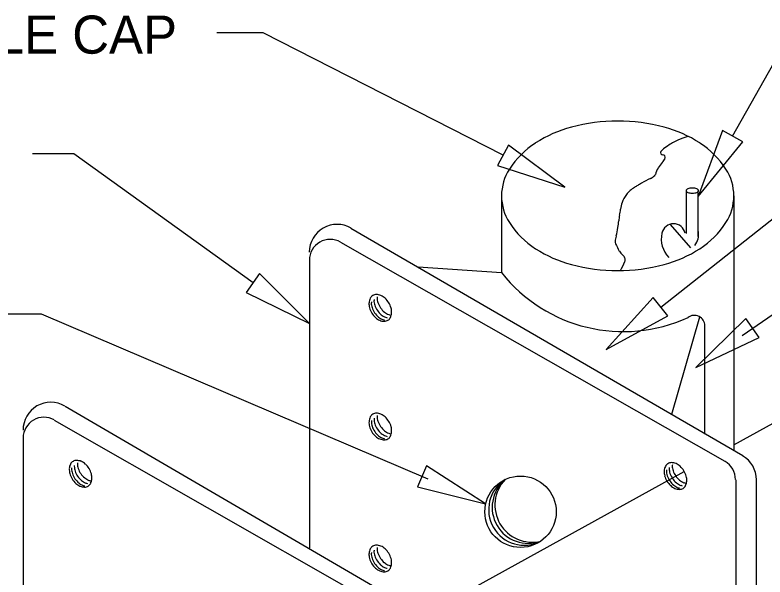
# Model space of a CAD drawing. Extents: x -1551.93 to -1544.71, y 2060.77 to 2070.61.
# Drawn here: x -1549.207 to -1548.026, y 2069.721 to 2070.606 of the extents above; entities that cross this region are included whole.
import ezdxf

# ---------------------------------------------------------------- set-up
doc = ezdxf.new("R2010")
doc.units = 0
for name, color, linetype in [('DETL-DIMS', 7, 'Continuous'), ('DETL-LINE', 7, 'Continuous'), ('DETL-NOTE', 7, 'Continuous')]:
    doc.layers.add(name, color=color, linetype=linetype)

msp = doc.modelspace()

# ---------------------------------------------------------------- linework, layer by layer
at = {"layer": 'DETL-DIMS'}
for p, q in [((-1548.0776, 2070.415), (-1547.9806, 2070.587)), ((-1548.8166, 2070.578), (-1548.8896, 2070.578)), ((-1548.4386, 2070.385), (-1548.8166, 2070.578)), ((-1548.1906, 2070.146), (-1547.8386, 2070.424)), ((-1549.1146, 2070.387), (-1549.1796, 2070.387)), ((-1548.8326, 2070.184), (-1549.1146, 2070.387)), ((-1548.0626, 2070.101), (-1547.8356, 2070.259)), ((-1549.1656, 2070.135), (-1549.4676, 2070.135)), ((-1548.5566, 2069.875), (-1549.1656, 2070.135)), ((-1548.0756, 2069.929), (-1547.9386, 2070.005)), ((-1548.5636, 2069.661), (-1548.1536, 2069.887))]:
    msp.add_line(p, q, dxfattribs=at)
for points in [[(-1548.0616, 2070.406), (-1548.0936, 2070.424), (-1548.1316, 2070.32)], [(-1548.4306, 2070.401), (-1548.4476, 2070.369), (-1548.3416, 2070.335)], [(-1548.8226, 2070.199), (-1548.8436, 2070.169), (-1548.7436, 2070.12)], [(-1548.1796, 2070.132), (-1548.2026, 2070.161), (-1548.2766, 2070.079)], [(-1548.0356, 2070.098), (-1548.0566, 2070.128), (-1548.1356, 2070.051)], [(-1548.5596, 2069.896), (-1548.5736, 2069.863), (-1548.4666, 2069.836)]]:
    msp.add_lwpolyline(points, close=True, dxfattribs=at)
at = {"layer": 'DETL-LINE'}
for p, q in [((-1548.1506, 2070.329), (-1548.1506, 2070.262)), ((-1548.1316, 2070.257), (-1548.1316, 2070.329)), ((-1548.4416, 2070.321), (-1548.4416, 2070.2)), ((-1548.0756, 2070.321), (-1548.0756, 2069.92)), ((-1548.6786, 2070.27), (-1548.0616, 2069.912)), ((-1548.1756, 2070.276), (-1548.1436, 2070.239)), ((-1548.6946, 2070.248), (-1548.0896, 2069.903)), ((-1548.7436, 2070.22), (-1548.7436, 2069.766)), ((-1548.4416, 2070.2), (-1548.5726, 2070.209)), ((-1548.1296, 2070.13), (-1548.1736, 2069.977)), ((-1548.1216, 2070.116), (-1548.1216, 2069.946)), ((-1549.1286, 2069.99), (-1548.5456, 2069.65)), ((-1549.1456, 2069.968), (-1548.5726, 2069.641)), ((-1549.1946, 2069.94), (-1549.1946, 2069.507)), ((-1548.0726, 2069.874), (-1548.0726, 2069.414)), ((-1548.0406, 2069.874), (-1548.0406, 2069.413))]:
    msp.add_line(p, q, dxfattribs=at)
msp.add_circle((-1548.4114, 2069.8236), 0.0562, dxfattribs=at)
for centre, radius, start, end in [((-1548.2584, 2070.1559), 0.283, 90, 104.9368), ((-1548.2584, 2070.1559), 0.283, 75.0632, 90), ((-1548.2801, 2070.2373), 0.1987, 104.9368, 122.7829), ((-1548.2367, 2070.2373), 0.1987, 57.2171, 75.0632), ((-1548.1225, 2070.3176), 0.1001, 114.4559, 124.7154), ((-1548.1223, 2070.3171), 0.1006, 104.2226, 114.4559), ((-1548.3133, 2070.2887), 0.1375, 122.7829, 147.2527), ((-1548.0875, 2070.267), 0.1616, 124.7154, 128.6761), ((-1548.2036, 2070.2887), 0.1375, 32.7473, 57.2171), ((-1548.1876, 2070.3891), 0.00345, 144.3395, 271.8271), ((-1548.1819, 2070.385), 0.0104, 128.6761, 144.3395), ((-1548.1873, 2070.3818), 0.00385, 335.5, 91.8271), ((-1548.1569, 2070.3436), 0.0434, 136.3012, 150.5406), ((-1548.2057, 2070.3901), 0.024, 316.3012, 335.5), ((-1548.3636, 2070.3211), 0.0777, 147.2527, 180), ((-1548.1478, 2070.3384), 0.0539, 150.5406, 162.2182), ((-1548.1533, 2070.3211), 0.0777, 0, 32.7473), ((-1548.1261, 2070.1799), 0.1869, 115.6278, 120.4952), ((-1548.2209, 2070.3775), 0.0323, 295.6278, 307.36), ((-1548.2051, 2070.3568), 0.00622, 307.36, 342.2182), ((-1547.9262, 2069.8365), 0.5842, 120.9785, 121.5501), ((-1547.8064, 2069.637), 0.8169, 120.4952, 120.9785), ((-1548.2053, 2070.2911), 0.0508, 121.5501, 140.727), ((-1548.149, 2070.3293), 0.00185, 134.8586, 180), ((-1548.149, 2070.3293), 0.00185, 180, 225.1414), ((-1548.1452, 2070.3255), 0.0072, 112.4002, 134.8586), ((-1548.1452, 2070.3331), 0.0072, 225.1414, 247.5998), ((-1548.1427, 2070.3194), 0.0139, 99.6886, 112.4002), ((-1548.1427, 2070.3393), 0.0139, 247.5998, 260.3114), ((-1548.141, 2070.3096), 0.0238, 90, 99.6886), ((-1548.141, 2070.3491), 0.0238, 260.3114, 270), ((-1548.141, 2070.3096), 0.0238, 80.3114, 90), ((-1548.141, 2070.3491), 0.0238, 270, 279.6886), ((-1548.1393, 2070.3194), 0.0139, 67.5998, 80.3114), ((-1548.1393, 2070.3393), 0.0139, 279.6886, 292.4002), ((-1548.1368, 2070.3255), 0.0072, 45.1414, 67.5998), ((-1548.1368, 2070.3331), 0.0072, 292.4002, 314.8586), ((-1548.133, 2070.3293), 0.00185, 0, 45.1414), ((-1548.133, 2070.3293), 0.00185, 314.8586, 0), ((-1548.3636, 2070.3211), 0.0777, 180, 212.7473), ((-1548.2153, 2070.2993), 0.0378, 140.727, 162.9839), ((-1548.1533, 2070.3211), 0.0777, 327.2527, 0), ((-1548.1539, 2070.2776), 0.1028, 167.4783, 172.6817), ((-1548.1197, 2070.2701), 0.1378, 162.9839, 167.4783), ((-1547.9716, 2070.2542), 0.2865, 172.6817, 174.5027), ((-1548.3133, 2070.3534), 0.1375, 212.7473, 237.2171), ((-1548.6472, 2070.3192), 0.3922, 352.9461, 354.5027), ((-1548.1705, 2070.2583), 0.0188, 12.4028, 167.5972), ((-1548.2036, 2070.3534), 0.1375, 302.7829, 327.2527), ((-1548.7002, 2070.2324), 0.0438, 59.8138, 180), ((-1548.329, 2070.2799), 0.0715, 342.0846, 352.9461), ((-1548.1613, 2070.261), 0.0304, 323.4347, 7.5849), ((-1548.7111, 2070.2198), 0.0328, 60.2969, 180), ((-1548.2327, 2070.2487), 0.0297, 162.0846, 178.9743), ((-1548.1478, 2070.2533), 0.042, 167.5972, 224.2626), ((-1548.2537, 2070.2491), 0.0087, 178.9743, 203.1865), ((-1548.159, 2070.2897), 0.1117, 203.1865, 209.8962), ((-1548.2801, 2070.4049), 0.1987, 237.2171, 255.0632), ((-1548.2365, 2070.2451), 0.0222, 209.8962, 231.1328), ((-1548.2367, 2070.4049), 0.1987, 284.9368, 302.7829), ((-1548.3679, 2070.2678), 0.1308, 330.4837, 337.392), ((-1548.2574, 2070.2191), 0.0111, 20.8484, 51.1328), ((-1548.2541, 2070.2204), 0.00755, 337.392, 20.8484), ((-1548.2584, 2070.4863), 0.283, 255.0632, 270), ((-1548.2584, 2070.4863), 0.283, 270, 284.9368), ((-1548.2495, 2070.3518), 0.2445, 218.3349, 294.647), ((-1548.6325, 2070.1517), 0.0175, 152.7723, 177.2015), ((-1548.6384, 2070.1548), 0.0109, 121.5859, 152.7723), ((-1548.6384, 2070.1548), 0.0109, 90.3995, 121.5859), ((-1548.6384, 2070.1481), 0.0175, 65.9703, 90.3995), ((-1548.6196, 2070.1607), 0.0175, 175.5761, 179.972), ((-1548.613, 2070.1607), 0.0242, 179.972, 198.5308), ((-1548.6411, 2070.142), 0.0242, 47.4114, 65.9703), ((-1548.6472, 2070.1354), 0.0332, 31.5859, 47.4114), ((-1548.6259, 2070.1514), 0.0242, 177.2015, 195.7604), ((-1548.6288, 2070.1527), 0.0175, 175.5761, 179.972), ((-1548.6222, 2070.1527), 0.0242, 179.972, 198.5308), ((-1548.6246, 2070.1564), 0.0175, 175.5761, 179.972), ((-1548.618, 2070.1564), 0.0242, 179.972, 198.5308), ((-1548.6094, 2070.1593), 0.0332, 198.5308, 214.3563), ((-1548.6045, 2070.1635), 0.0332, 198.5308, 214.3563), ((-1548.6472, 2070.1354), 0.0332, 15.7604, 31.5859), ((-1548.6172, 2070.1538), 0.0332, 195.7604, 211.5859), ((-1548.6172, 2070.1538), 0.0332, 211.5859, 227.4114), ((-1548.6137, 2070.1556), 0.0332, 198.5308, 214.3563), ((-1548.6137, 2070.1556), 0.0332, 214.3563, 230.1818), ((-1548.6094, 2070.1593), 0.0332, 214.3563, 230.1818), ((-1548.6045, 2070.1635), 0.0332, 214.3563, 230.1818), ((-1548.6102, 2070.1566), 0.0242, 230.1818, 248.7407), ((-1548.6319, 2070.1375), 0.0175, 332.7723, 357.2015), ((-1548.6385, 2070.1378), 0.0242, 357.2015, 15.7604), ((-1548.6233, 2070.1472), 0.0242, 227.4114, 245.9703), ((-1548.6194, 2070.1487), 0.0242, 230.1818, 248.7407), ((-1548.626, 2070.1411), 0.0175, 245.9703, 270.3995), ((-1548.6152, 2070.1524), 0.0242, 230.1818, 248.7407), ((-1548.6218, 2070.1425), 0.0175, 248.7407, 257.6351), ((-1548.6259, 2070.1345), 0.0109, 270.3995, 301.5859), ((-1548.6176, 2070.1462), 0.0175, 248.7407, 257.6351), ((-1548.6259, 2070.1345), 0.0109, 301.5859, 332.7723), ((-1548.6126, 2070.1504), 0.0175, 248.7407, 257.6351), ((-1548.1376, 2070.1165), 0.0164, 0, 127.5357), ((-1549.1509, 2069.9522), 0.0438, 59.8138, 180), ((-1549.1618, 2069.9396), 0.0328, 60.2969, 180), ((-1548.6324, 2069.9648), 0.0175, 152.7723, 177.2015), ((-1548.6384, 2069.9679), 0.0109, 121.5859, 152.7723), ((-1548.6384, 2069.9679), 0.0109, 90.3995, 121.5859), ((-1548.6245, 2069.9696), 0.0175, 175.5761, 179.972), ((-1548.6179, 2069.9696), 0.0242, 179.972, 198.5308), ((-1548.6383, 2069.9612), 0.0175, 65.9703, 90.3995), ((-1548.6196, 2069.9738), 0.0175, 175.5761, 179.972), ((-1548.613, 2069.9738), 0.0242, 179.972, 198.5308), ((-1548.641, 2069.9551), 0.0242, 47.4114, 65.9703), ((-1548.6471, 2069.9485), 0.0332, 31.5859, 47.4114), ((-1548.6258, 2069.9645), 0.0242, 177.2015, 195.7604), ((-1548.6172, 2069.9669), 0.0332, 195.7604, 211.5859), ((-1548.6288, 2069.9659), 0.0175, 175.5761, 179.972), ((-1548.6221, 2069.9658), 0.0242, 179.972, 198.5308), ((-1548.6136, 2069.9687), 0.0332, 198.5308, 214.3563), ((-1548.6094, 2069.9724), 0.0332, 198.5308, 214.3563), ((-1548.6044, 2069.9767), 0.0332, 198.5308, 214.3563), ((-1548.6044, 2069.9767), 0.0332, 214.3563, 230.1818), ((-1548.6471, 2069.9485), 0.0332, 15.7604, 31.5859), ((-1548.6385, 2069.951), 0.0242, 357.2015, 15.7604), ((-1548.6172, 2069.9669), 0.0332, 211.5859, 227.4114), ((-1548.6136, 2069.9687), 0.0332, 214.3563, 230.1818), ((-1548.6094, 2069.9724), 0.0332, 214.3563, 230.1818), ((-1548.6151, 2069.9655), 0.0242, 230.1818, 248.7407), ((-1548.6102, 2069.9698), 0.0242, 230.1818, 248.7407), ((-1548.6126, 2069.9636), 0.0175, 248.7407, 257.6351), ((-1548.6318, 2069.9506), 0.0175, 332.7723, 357.2015), ((-1548.6232, 2069.9603), 0.0242, 227.4114, 245.9703), ((-1548.6194, 2069.9618), 0.0242, 230.1818, 248.7407), ((-1548.6259, 2069.9543), 0.0175, 245.9703, 270.3995), ((-1548.6218, 2069.9556), 0.0175, 248.7407, 257.6351), ((-1548.6259, 2069.9476), 0.0109, 270.3995, 301.5859), ((-1548.6175, 2069.9593), 0.0175, 248.7407, 257.6351), ((-1548.6259, 2069.9476), 0.0109, 301.5859, 332.7723), ((-1548.0838, 2069.8738), 0.0438, 0, 59.8138), ((-1549.1044, 2069.8906), 0.0175, 152.7723, 177.2015), ((-1549.1103, 2069.8936), 0.0109, 121.5859, 152.7723), ((-1549.1103, 2069.8936), 0.0109, 90.3995, 121.5859), ((-1549.1103, 2069.8869), 0.0175, 65.9703, 90.3995), ((-1549.0915, 2069.8995), 0.0175, 175.5761, 179.972), ((-1549.0849, 2069.8995), 0.0242, 179.972, 198.5308), ((-1549.113, 2069.8809), 0.0242, 47.4114, 65.9703), ((-1549.119, 2069.8743), 0.0332, 31.5859, 47.4114), ((-1548.1737, 2069.89), 0.0109, 121.5859, 152.7723), ((-1548.1737, 2069.89), 0.0109, 90.3995, 121.5859), ((-1548.1736, 2069.8834), 0.0175, 65.9703, 90.3995), ((-1548.1763, 2069.8773), 0.0242, 47.4114, 65.9703), ((-1548.1057, 2069.8744), 0.0328, 0, 60.2969), ((-1549.0977, 2069.8902), 0.0242, 177.2015, 195.7604), ((-1549.1007, 2069.8916), 0.0175, 175.5761, 179.972), ((-1549.0941, 2069.8916), 0.0242, 179.972, 198.5308), ((-1549.0965, 2069.8953), 0.0175, 175.5761, 179.972), ((-1549.0898, 2069.8953), 0.0242, 179.972, 198.5308), ((-1549.0813, 2069.8982), 0.0332, 198.5308, 214.3563), ((-1549.0764, 2069.9024), 0.0332, 198.5308, 214.3563), ((-1549.119, 2069.8743), 0.0332, 15.7604, 31.5859), ((-1548.1678, 2069.887), 0.0175, 152.7723, 177.2015), ((-1548.1611, 2069.8867), 0.0242, 177.2015, 195.7604), ((-1548.1641, 2069.888), 0.0175, 175.5761, 179.972), ((-1548.1575, 2069.888), 0.0242, 179.972, 198.5308), ((-1548.1599, 2069.8917), 0.0175, 175.5761, 179.972), ((-1548.1532, 2069.8917), 0.0242, 179.972, 198.5308), ((-1548.1549, 2069.896), 0.0175, 175.5761, 179.972), ((-1548.1483, 2069.896), 0.0242, 179.972, 198.5308), ((-1548.1397, 2069.8988), 0.0332, 198.5308, 214.3563), ((-1548.1824, 2069.8707), 0.0332, 31.5859, 47.4114), ((-1548.1824, 2069.8707), 0.0332, 15.7604, 31.5859), ((-1549.0891, 2069.8927), 0.0332, 195.7604, 211.5859), ((-1549.0891, 2069.8927), 0.0332, 211.5859, 227.4114), ((-1549.0855, 2069.8944), 0.0332, 198.5308, 214.3563), ((-1549.0855, 2069.8944), 0.0332, 214.3563, 230.1818), ((-1549.0813, 2069.8982), 0.0332, 214.3563, 230.1818), ((-1549.0764, 2069.9024), 0.0332, 214.3563, 230.1818), ((-1549.0821, 2069.8955), 0.0242, 230.1818, 248.7407), ((-1549.1038, 2069.8764), 0.0175, 332.7723, 357.2015), ((-1549.1104, 2069.8767), 0.0242, 357.2015, 15.7604), ((-1548.1525, 2069.8891), 0.0332, 195.7604, 211.5859), ((-1548.1489, 2069.8909), 0.0332, 198.5308, 214.3563), ((-1548.1447, 2069.8946), 0.0332, 198.5308, 214.3563), ((-1548.1447, 2069.8946), 0.0332, 214.3563, 230.1818), ((-1548.1397, 2069.8988), 0.0332, 214.3563, 230.1818), ((-1548.1738, 2069.8731), 0.0242, 357.2015, 15.7604), ((-1549.0952, 2069.8861), 0.0242, 227.4114, 245.9703), ((-1549.0913, 2069.8875), 0.0242, 230.1818, 248.7407), ((-1549.0979, 2069.88), 0.0175, 245.9703, 270.3995), ((-1549.0871, 2069.8913), 0.0242, 230.1818, 248.7407), ((-1549.0937, 2069.8814), 0.0175, 248.7407, 257.6351), ((-1549.0978, 2069.8733), 0.0109, 270.3995, 301.5859), ((-1549.0895, 2069.8851), 0.0175, 248.7407, 257.6351), ((-1549.0978, 2069.8733), 0.0109, 301.5859, 332.7723), ((-1549.0845, 2069.8893), 0.0175, 248.7407, 257.6351), ((-1548.4055, 2069.827), 0.0561, 122.664, 297.7204), ((-1548.3993, 2069.8306), 0.0568, 129.8655, 290.5188), ((-1548.3933, 2069.8341), 0.0584, 136.5705, 283.8138), ((-1548.1525, 2069.8891), 0.0332, 211.5859, 227.4114), ((-1548.1489, 2069.8909), 0.0332, 214.3563, 230.1818), ((-1548.1586, 2069.8825), 0.0242, 227.4114, 245.9703), ((-1548.1547, 2069.884), 0.0242, 230.1818, 248.7407), ((-1548.1505, 2069.8877), 0.0242, 230.1818, 248.7407), ((-1548.1455, 2069.8919), 0.0242, 230.1818, 248.7407), ((-1548.1529, 2069.8815), 0.0175, 248.7407, 257.6351), ((-1548.1612, 2069.8697), 0.0109, 301.5859, 332.7723), ((-1548.1479, 2069.8857), 0.0175, 248.7407, 257.6351), ((-1548.1672, 2069.8728), 0.0175, 332.7723, 357.2015), ((-1548.1613, 2069.8764), 0.0175, 245.9703, 270.3995), ((-1548.1571, 2069.8778), 0.0175, 248.7407, 257.6351), ((-1548.1612, 2069.8697), 0.0109, 270.3995, 301.5859), ((-1548.6384, 2069.7601), 0.0109, 121.5859, 152.7723), ((-1548.6384, 2069.7601), 0.0109, 90.3995, 121.5859), ((-1548.6384, 2069.7534), 0.0175, 65.9703, 90.3995), ((-1548.6411, 2069.7474), 0.0242, 47.4114, 65.9703), ((-1548.6325, 2069.7571), 0.0175, 152.7723, 177.2015), ((-1548.6259, 2069.7567), 0.0242, 177.2015, 195.7604), ((-1548.6288, 2069.7581), 0.0175, 175.5761, 179.972), ((-1548.6222, 2069.7581), 0.0242, 179.972, 198.5308), ((-1548.6246, 2069.7618), 0.0175, 175.5761, 179.972), ((-1548.618, 2069.7618), 0.0242, 179.972, 198.5308), ((-1548.6196, 2069.766), 0.0175, 175.5761, 179.972), ((-1548.613, 2069.766), 0.0242, 179.972, 198.5308), ((-1548.6045, 2069.7689), 0.0332, 198.5308, 214.3563), ((-1548.6472, 2069.7408), 0.0332, 31.5859, 47.4114), ((-1548.6472, 2069.7408), 0.0332, 15.7604, 31.5859), ((-1548.6172, 2069.7592), 0.0332, 195.7604, 211.5859), ((-1548.6137, 2069.7609), 0.0332, 198.5308, 214.3563), ((-1548.6094, 2069.7647), 0.0332, 198.5308, 214.3563), ((-1548.6094, 2069.7647), 0.0332, 214.3563, 230.1818), ((-1548.6045, 2069.7689), 0.0332, 214.3563, 230.1818), ((-1548.6385, 2069.7432), 0.0242, 357.2015, 15.7604), ((-1548.6172, 2069.7592), 0.0332, 211.5859, 227.4114), ((-1548.6137, 2069.7609), 0.0332, 214.3563, 230.1818), ((-1548.6233, 2069.7526), 0.0242, 227.4114, 245.9703), ((-1548.6194, 2069.754), 0.0242, 230.1818, 248.7407), ((-1548.6152, 2069.7578), 0.0242, 230.1818, 248.7407), ((-1548.6102, 2069.762), 0.0242, 230.1818, 248.7407), ((-1548.6176, 2069.7516), 0.0175, 248.7407, 257.6351), ((-1548.6259, 2069.7398), 0.0109, 301.5859, 332.7723), ((-1548.6126, 2069.7558), 0.0175, 248.7407, 257.6351), ((-1548.6319, 2069.7429), 0.0175, 332.7723, 357.2015), ((-1548.626, 2069.7465), 0.0175, 245.9703, 270.3995), ((-1548.6218, 2069.7479), 0.0175, 248.7407, 257.6351), ((-1548.6259, 2069.7398), 0.0109, 270.3995, 301.5859)]:
    msp.add_arc(centre, radius, start, end, dxfattribs=at)

# ---------------------------------------------------------------- texts
at = {"layer": 'DETL-NOTE'}
msp.add_text('POLE CAP', height=0.06, dxfattribs=at).set_placement((-1549.3536, 2070.545))

doc.saveas('drawing.dxf')
